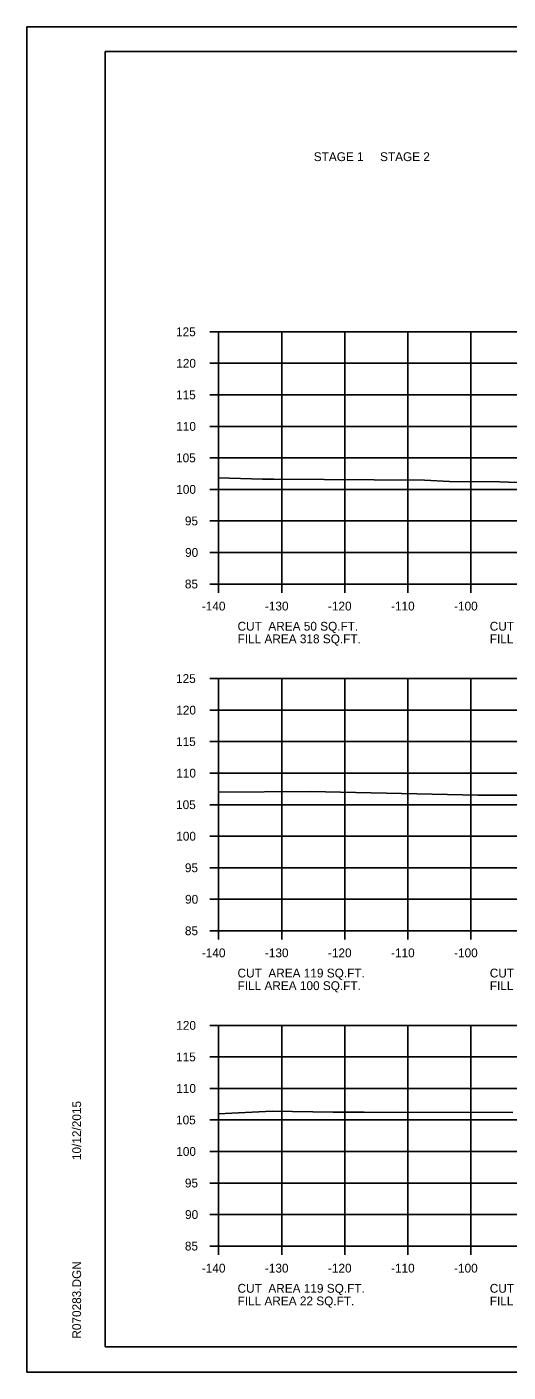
# Model space of a CAD drawing. Extents: x 1175611 to 1176402, y -433344 to -416213.
# Drawn here: x 1175610.6 to 1175686.9, y -430996.8 to -430783.5 of the extents above; entities that cross this region are included whole.
import ezdxf

# ---------------------------------------------------------------- set-up
doc = ezdxf.new("R2010")
doc.units = 0
for name, color, linetype in [('Default', 7, 'Continuous'), ('R_Axis', 7, 'Continuous'), ('R_Axis Annot', 7, 'Continuous'), ('R_Border', 7, 'Continuous'), ('R_Exist Surface', 7, 'Continuous'), ('R_Grid', 7, 'Continuous'), ('R_No Plot', 7, 'Continuous')]:
    doc.layers.add(name, color=color, linetype=linetype)

msp = doc.modelspace()

# ---------------------------------------------------------------- linework, layer by layer
at = {"layer": 'R_Axis'}
for p, q in [((1175639.57, -430831.83), (1175640.97, -430831.83)), ((1175640.97, -430871.83), (1175640.97, -430831.83)), ((1175639.57, -430836.83), (1175640.97, -430836.83)), ((1175639.57, -430841.83), (1175640.97, -430841.83)), ((1175639.57, -430846.83), (1175640.97, -430846.83)), ((1175639.57, -430851.83), (1175640.97, -430851.83)), ((1175639.57, -430856.83), (1175640.97, -430856.83)), ((1175639.57, -430861.83), (1175640.97, -430861.83)), ((1175639.57, -430866.83), (1175640.97, -430866.83)), ((1175639.57, -430871.83), (1175640.97, -430871.83)), ((1175640.97, -430871.83), (1175920.97, -430871.83)), ((1175640.97, -430873.23), (1175640.97, -430871.83)), ((1175650.97, -430873.23), (1175650.97, -430871.83)), ((1175660.97, -430873.23), (1175660.97, -430871.83)), ((1175670.97, -430873.23), (1175670.97, -430871.83)), ((1175680.97, -430873.23), (1175680.97, -430871.83)), ((1175639.57, -430886.83), (1175640.97, -430886.83)), ((1175640.97, -430926.83), (1175640.97, -430886.83)), ((1175639.57, -430891.83), (1175640.97, -430891.83)), ((1175639.57, -430896.83), (1175640.97, -430896.83)), ((1175639.57, -430901.83), (1175640.97, -430901.83)), ((1175639.57, -430906.83), (1175640.97, -430906.83)), ((1175639.57, -430911.83), (1175640.97, -430911.83)), ((1175639.57, -430916.83), (1175640.97, -430916.83)), ((1175639.57, -430921.83), (1175640.97, -430921.83)), ((1175639.57, -430926.83), (1175640.97, -430926.83)), ((1175640.97, -430926.83), (1175920.97, -430926.83)), ((1175640.97, -430928.23), (1175640.97, -430926.83)), ((1175650.97, -430928.23), (1175650.97, -430926.83)), ((1175660.97, -430928.23), (1175660.97, -430926.83)), ((1175670.97, -430928.23), (1175670.97, -430926.83)), ((1175680.97, -430928.23), (1175680.97, -430926.83)), ((1175639.57, -430941.83), (1175640.97, -430941.83)), ((1175640.97, -430976.83), (1175640.97, -430941.83)), ((1175639.57, -430946.83), (1175640.97, -430946.83)), ((1175639.57, -430951.83), (1175640.97, -430951.83)), ((1175639.57, -430956.83), (1175640.97, -430956.83)), ((1175639.57, -430961.83), (1175640.97, -430961.83)), ((1175639.57, -430966.83), (1175640.97, -430966.83)), ((1175639.57, -430971.83), (1175640.97, -430971.83)), ((1175639.57, -430976.83), (1175640.97, -430976.83)), ((1175640.97, -430976.83), (1175920.97, -430976.83)), ((1175640.97, -430978.23), (1175640.97, -430976.83)), ((1175650.97, -430978.23), (1175650.97, -430976.83)), ((1175660.97, -430978.23), (1175660.97, -430976.83)), ((1175670.97, -430978.23), (1175670.97, -430976.83)), ((1175680.97, -430978.23), (1175680.97, -430976.83))]:
    msp.add_line(p, q, dxfattribs=at)
at = {"layer": 'R_Border'}
for p, q in [((1175622.97, -430787.37), (1175939.15, -430787.37)), ((1175622.97, -430992.83), (1175622.97, -430787.37)), ((1175622.97, -430992.83), (1175622.97, -430992.83)), ((1175939.15, -430992.83), (1175622.97, -430992.83))]:
    msp.add_line(p, q, dxfattribs=at)
at = {"layer": 'R_Exist Surface'}
for points in [[(1175640.97, -430855), (1175647.94, -430855.21), (1175649.72, -430855.22), (1175673.63, -430855.38), (1175677.58, -430855.56), (1175685.49, -430855.6), (1175711.63, -430856.59)], [(1175640.97, -430904.82), (1175655.49, -430904.76), (1175682.07, -430905.31), (1175692.63, -430905.34)], [(1175640.97, -430955.86), (1175649.45, -430955.41), (1175659.12, -430955.58), (1175664.03, -430955.59), (1175687.64, -430955.66)]]:
    msp.add_lwpolyline(points, dxfattribs=at)
at = {"layer": 'R_Grid'}
for p, q in [((1175640.97, -430831.83), (1175920.97, -430831.83)), ((1175640.97, -430871.83), (1175640.97, -430831.83)), ((1175650.97, -430871.83), (1175650.97, -430831.83)), ((1175660.97, -430871.83), (1175660.97, -430831.83)), ((1175670.97, -430871.83), (1175670.97, -430831.83)), ((1175680.97, -430871.83), (1175680.97, -430831.83)), ((1175640.97, -430836.83), (1175920.97, -430836.83)), ((1175640.97, -430841.83), (1175920.97, -430841.83)), ((1175640.97, -430846.83), (1175920.97, -430846.83)), ((1175640.97, -430851.83), (1175920.97, -430851.83)), ((1175640.97, -430856.83), (1175920.97, -430856.83)), ((1175640.97, -430861.83), (1175920.97, -430861.83)), ((1175640.97, -430866.83), (1175920.97, -430866.83)), ((1175640.97, -430871.83), (1175920.97, -430871.83)), ((1175640.97, -430886.83), (1175920.97, -430886.83)), ((1175640.97, -430926.83), (1175640.97, -430886.83)), ((1175650.97, -430926.83), (1175650.97, -430886.83)), ((1175660.97, -430926.83), (1175660.97, -430886.83)), ((1175670.97, -430926.83), (1175670.97, -430886.83)), ((1175680.97, -430926.83), (1175680.97, -430886.83)), ((1175640.97, -430891.83), (1175920.97, -430891.83)), ((1175640.97, -430896.83), (1175920.97, -430896.83)), ((1175640.97, -430901.83), (1175920.97, -430901.83)), ((1175640.97, -430906.83), (1175920.97, -430906.83)), ((1175640.97, -430911.83), (1175920.97, -430911.83)), ((1175640.97, -430916.83), (1175920.97, -430916.83)), ((1175640.97, -430921.83), (1175920.97, -430921.83)), ((1175640.97, -430926.83), (1175920.97, -430926.83)), ((1175640.97, -430941.83), (1175920.97, -430941.83)), ((1175640.97, -430976.83), (1175640.97, -430941.83)), ((1175650.97, -430976.83), (1175650.97, -430941.83)), ((1175660.97, -430976.83), (1175660.97, -430941.83)), ((1175670.97, -430976.83), (1175670.97, -430941.83)), ((1175680.97, -430976.83), (1175680.97, -430941.83)), ((1175640.97, -430946.83), (1175920.97, -430946.83)), ((1175640.97, -430951.83), (1175920.97, -430951.83)), ((1175640.97, -430956.83), (1175920.97, -430956.83)), ((1175640.97, -430961.83), (1175920.97, -430961.83)), ((1175640.97, -430966.83), (1175920.97, -430966.83)), ((1175640.97, -430971.83), (1175920.97, -430971.83)), ((1175640.97, -430976.83), (1175920.97, -430976.83))]:
    msp.add_line(p, q, dxfattribs=at)
at = {"layer": 'R_No Plot'}
for p, q in [((1175610.57, -430783.48), (1175943.91, -430783.48)), ((1175610.57, -430996.81), (1175943.91, -430996.81))]:
    msp.add_line(p, q, dxfattribs=at)
msp.add_lwpolyline([(1175610.57, -430783.48), (1175943.91, -430783.48), (1175943.91, -430996.82), (1175610.57, -430996.82)], close=True, dxfattribs=at)

# ---------------------------------------------------------------- texts
at = {"layer": 'Default'}
for s, p in [('STAGE 1     STAGE 2', (1175656.06, -430804.76)), ('CUT  AREA 50 SQ.FT.', (1175643.97, -430879.23)), ('CUT  AREA 392 SQ.FT.', (1175683.97, -430879.23)), ('FILL AREA 318 SQ.FT.', (1175643.97, -430881.23)), ('FILL AREA 334 SQ.FT.', (1175683.97, -430881.23)), ('CUT  AREA 119 SQ.FT.', (1175643.97, -430934.23)), ('CUT  AREA 0 SQ.FT.', (1175683.97, -430934.23)), ('FILL AREA 100 SQ.FT.', (1175643.97, -430936.23)), ('FILL AREA 224 SQ.FT.', (1175683.97, -430936.23)), ('CUT  AREA 119 SQ.FT.', (1175643.97, -430984.23)), ('CUT  AREA 1 SQ.FT.', (1175683.97, -430984.23)), ('FILL AREA 22 SQ.FT.', (1175643.97, -430986.23)), ('FILL AREA 199 SQ.FT.', (1175683.97, -430986.23))]:
    msp.add_text(s, height=1.4, dxfattribs=at).set_placement(p)
at = {"layer": 'R_Axis Annot'}
for s, p in [('125', (1175634.22, -430832.53)), ('120', (1175634.25, -430837.53)), ('115', (1175634.22, -430842.53)), ('110', (1175634.25, -430847.53)), ('105', (1175634.22, -430852.53)), ('100', (1175634.25, -430857.53)), ('95', (1175635.62, -430862.53)), ('90', (1175635.65, -430867.53)), ('85', (1175635.62, -430872.53)), ('-140', (1175638.31, -430876.03)), ('-130', (1175648.31, -430876.03)), ('-120', (1175658.31, -430876.03)), ('-110', (1175668.31, -430876.03)), ('-100', (1175678.31, -430876.03)), ('125', (1175634.22, -430887.53)), ('120', (1175634.25, -430892.53)), ('115', (1175634.22, -430897.53)), ('110', (1175634.25, -430902.53)), ('105', (1175634.22, -430907.53)), ('100', (1175634.25, -430912.53)), ('95', (1175635.62, -430917.53)), ('90', (1175635.65, -430922.53)), ('85', (1175635.62, -430927.53)), ('-140', (1175638.31, -430931.03)), ('-130', (1175648.31, -430931.03)), ('-120', (1175658.31, -430931.03)), ('-110', (1175668.31, -430931.03)), ('-100', (1175678.31, -430931.03)), ('120', (1175634.25, -430942.53)), ('115', (1175634.22, -430947.53)), ('110', (1175634.25, -430952.53)), ('105', (1175634.22, -430957.53)), ('100', (1175634.25, -430962.53)), ('95', (1175635.62, -430967.53)), ('90', (1175635.65, -430972.53)), ('85', (1175635.62, -430977.53)), ('-140', (1175638.31, -430981.03)), ('-130', (1175648.31, -430981.03)), ('-120', (1175658.31, -430981.03)), ('-110', (1175668.31, -430981.03)), ('-100', (1175678.31, -430981.03))]:
    msp.add_text(s, height=1.4, dxfattribs=at).set_placement(p)
at = {"layer": 'R_Border'}
for s, p in [('10/12/2015', (1175619.16, -430963.19)), ('R070283.DGN', (1175619.16, -430991.51))]:
    msp.add_text(s, height=1.4, rotation=90, dxfattribs=at).set_placement(p)

doc.saveas('drawing.dxf')
